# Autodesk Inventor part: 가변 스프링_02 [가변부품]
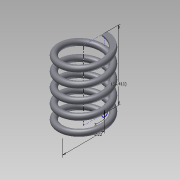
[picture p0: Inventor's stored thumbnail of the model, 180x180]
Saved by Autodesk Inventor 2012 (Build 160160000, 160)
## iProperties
Created: 2015-05
Part Number: 가변 스프링_02 [가변부품]
Material: 탄소강
Document SubType Name: Modeling
Designer: Administrator
Density: 7.87 g/cm^3
Mass: 18.8942 g
Surface Area: 32.5507 cm^2
Volume: 2.40079 cm^3
Author: Administrator
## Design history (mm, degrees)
sketch "스케치2"
  geometry: L1 (0, 0)-(11, 0); L2 (11, 0)-(11, 36.411); L3 (11, 36.411)-(0, 36.411); L4 (0, 36.411)-(0, 0); C1 r 1.5 at (11, 0)
  constraints: 8 end point, 2 parallel, 1 centre point, 1 coincident, 1 horizontal, 1 perpendicular
  dimensions: "d0" = 22 diameter of L2 L4; "d1" = 36.4112 distance of L1.end L2.end (derived); "d2" = 3 diameter of C1
feature "코일1" pitch "d3" = 10; turns "d5" = 5; dims "d4" = 36.4112 (= d1), "d6" = 0, angle "d7" = 90 deg, angle "d8" = 90 deg, "d9" = 0, "d10" = 0
sketch "스케치3"
  geometry: L1 (0, 12.5)-(0, 9.5) reference; 1 further point
  constraints: 1 vertical alignment
extrude "돌출1" cut sketch "스케치3" stored distance "d11" = 10; taper "d12" = 0 deg
node "작업 평면1"
sketch "스케치4"
  geometry: L1 (0, 12.5)-(0, 9.5) reference; 1 further point
  constraints: 1 vertical alignment
extrude "돌출2" cut sketch "스케치4" stored distance "d13" = 10; taper "d14" = 0 deg
node "솔리드1"
node "절단 모서리 투영1"
node "절단 모서리 투영2"
